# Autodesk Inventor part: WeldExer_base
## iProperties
Shininess: 64.0
Length Units: 11269
Angle Units: 11279
Time Units: 11290
Mass Units: 11286
Length Display Precision: 3
Angle Display Precision: 2
Compacted: True
Part Number: WeldExer_base
Document SubType Name: Modeling
Created: 2003-07
Designer: Ronald Myers
Manufacturer: Standard
Standards Organization: Custom
Stock Number: WeldExer_base
Density: 1 g/cm^3
Density: 0.0
Volumn: 0.0
Area: 0.0
PropertySet Name: Model Information
Control State: 0
Master: False
Checked Out: False
Author: Ronald Myers
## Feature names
1. Extrusion1
2. Hole1
3. Hole2
4. Hole3
5. Fillet1
